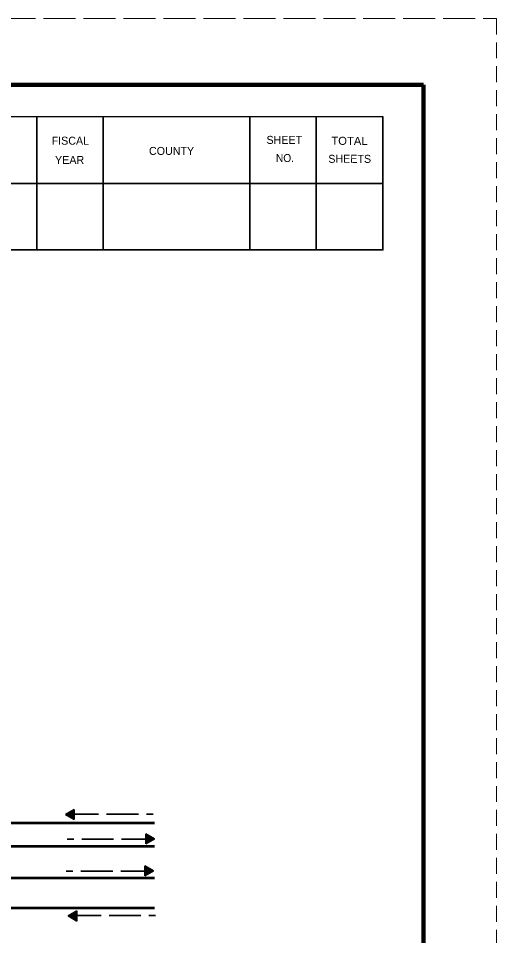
# Model space of a CAD drawing. Extents: x -58 to 622, y -372 to 68.
# Drawn here: x 549.8 to 621.6, y -69.7 to 68 of the extents above; entities that cross this region are included whole.
import ezdxf

# ---------------------------------------------------------------- set-up
doc = ezdxf.new("R2010")
doc.units = 0
doc.header["$LTSCALE"] = 0.8
doc.linetypes.add('LONG_DASHED', pattern=[7.5, 6, -1.5])
doc.linetypes.add('MEDIUM_DASHED', pattern=[4.5, 3, -1.5])
doc.layers.add('1', color=7, linetype='Continuous', lineweight=35)
doc.layers.add('61', color=7, linetype='Continuous', lineweight=35)

msp = doc.modelspace()

# ---------------------------------------------------------------- linework, layer by layer
at = {"layer": '1', "linetype": 'MEDIUM_DASHED', "lineweight": 13}
msp.add_line((621.5902, 67.9933), (621.5702, -372.0267), dxfattribs=at)
at = {"layer": '1'}
for p, q in [((558.1721, -50.7385), (556.8639, -51.4939)), ((557.8482, -52.0287), (557.8483, -50.9328)), ((557.8726, -52.0423), (557.8726, -50.919)), ((557.8971, -52.0561), (557.8971, -50.9051)), ((557.9055, -52.0607), (557.9056, -50.9003)), ((557.9422, -52.0815), (557.9424, -50.8794)), ((557.9652, -52.0943), (557.9652, -50.8665)), ((557.9791, -52.1021), (557.9792, -50.8587)), ((558.0013, -52.1145), (558.0013, -50.8461)), ((558.0364, -52.1343), (558.0364, -50.8262)), ((558.0632, -52.1493), (558.0632, -50.8109)), ((558.0952, -52.1674), (558.0952, -50.7928)), ((558.1089, -52.1749), (558.109, -50.7851)), ((558.1286, -52.1779), (558.1286, -50.788)), ((558.1503, -52.1983), (558.1503, -50.7616)), ((558.162, -52.2237), (558.1619, -50.7624)), ((558.1722, -52.2492), (558.1721, -50.7385)), ((558.1722, -52.2492), (556.8639, -51.4939)), ((556.915, -51.5046), (556.915, -51.4614)), ((556.9456, -51.5217), (556.9456, -51.444)), ((556.9711, -51.5359), (556.9711, -51.4296)), ((556.9909, -51.5471), (556.9908, -51.4184)), ((557.0132, -51.5596), (557.0132, -51.4057)), ((557.0269, -51.5674), (557.0268, -51.398)), ((557.0556, -51.5834), (557.0556, -51.3817)), ((557.1008, -51.6089), (557.1008, -51.3562)), ((557.1323, -51.6265), (557.1322, -51.3383)), ((557.1798, -51.6532), (557.1798, -51.3114)), ((557.2252, -51.6787), (557.2251, -51.2857)), ((557.254, -51.6948), (557.254, -51.2693)), ((557.2802, -51.7096), (557.2802, -51.2546)), ((557.3108, -51.7268), (557.311, -51.2372)), ((557.3392, -51.7428), (557.3393, -51.221)), ((557.3731, -51.7617), (557.3731, -51.202)), ((557.4037, -51.779), (557.4037, -51.1846)), ((557.4312, -51.7945), (557.4312, -51.1689)), ((557.4726, -51.8177), (557.4726, -51.1456)), ((557.4939, -51.8296), (557.494, -51.1333)), ((557.5322, -51.8511), (557.5322, -51.1118)), ((557.5675, -51.8708), (557.5672, -51.0918)), ((557.6078, -51.8937), (557.6078, -51.0689)), ((557.6461, -51.9151), (557.6462, -51.0472)), ((557.6735, -51.9305), (557.6734, -51.0317)), ((557.7005, -51.9457), (557.7005, -51.0163)), ((557.7273, -51.9606), (557.7273, -51.0013)), ((557.7441, -51.97), (557.7441, -50.9917)), ((557.7663, -51.9826), (557.7663, -50.979)), ((557.7898, -51.9958), (557.7899, -50.9659)), ((557.8175, -52.0113), (557.8176, -50.9501)), ((568.9053, -54.3872), (570.2136, -55.1424)), ((568.9053, -54.3872), (568.9054, -55.8978)), ((568.9155, -54.4127), (568.9156, -55.8739)), ((568.9272, -54.4381), (568.9272, -55.8747)), ((568.9489, -54.4584), (568.9489, -55.8483)), ((568.9686, -54.4614), (568.9685, -55.8513)), ((568.9823, -54.4689), (568.9823, -55.8435)), ((569.0143, -54.487), (569.0142, -55.8254)), ((569.0411, -54.5021), (569.0411, -55.8102)), ((569.0762, -54.5218), (569.0762, -55.7903)), ((569.0984, -54.5343), (569.0983, -55.7777)), ((569.1123, -54.542), (569.1123, -55.7698)), ((569.1352, -54.5548), (569.1351, -55.7569)), ((569.172, -54.5757), (569.1719, -55.736)), ((569.1804, -54.5802), (569.1804, -55.7312)), ((569.2049, -54.594), (569.2049, -55.7173)), ((569.2293, -54.6077), (569.2292, -55.7035)), ((569.26, -54.625), (569.2599, -55.6863)), ((569.2877, -54.6406), (569.2876, -55.6704)), ((569.3112, -54.6537), (569.3112, -55.6573)), ((569.3334, -54.6663), (569.3334, -55.6446)), ((569.3502, -54.6758), (569.3502, -55.635)), ((569.377, -54.6907), (569.377, -55.62)), ((569.404, -54.7058), (569.4041, -55.6046)), ((569.4314, -54.7212), (569.4313, -55.5891)), ((569.4697, -54.7426), (569.4697, -55.5674)), ((569.51, -54.7655), (569.5102, -55.5445)), ((569.5453, -54.7852), (569.5453, -55.5245)), ((569.5836, -54.8068), (569.5835, -55.503)), ((569.6049, -54.8187), (569.6049, -55.4907)), ((569.6463, -54.8418), (569.6463, -55.4674)), ((569.6738, -54.8573), (569.6738, -55.4517)), ((569.7044, -54.8746), (569.7044, -55.4343)), ((569.7382, -54.8936), (569.7382, -55.4153)), ((569.7667, -54.9095), (569.7665, -55.3992)), ((569.7973, -54.9267), (569.7973, -55.3817)), ((569.8235, -54.9415), (569.8235, -55.367)), ((569.8523, -54.9577), (569.8524, -55.3507)), ((569.8977, -54.9831), (569.8977, -55.3249)), ((569.9452, -55.0098), (569.9452, -55.298)), ((569.9767, -55.0274), (569.9767, -55.2802)), ((570.0219, -55.0529), (570.0219, -55.2546)), ((568.9054, -55.8978), (570.2136, -55.1424)), ((570.0506, -55.0689), (570.0507, -55.2383)), ((570.0643, -55.0767), (570.0643, -55.2306)), ((570.0866, -55.0892), (570.0867, -55.2179)), ((570.1064, -55.1004), (570.1064, -55.2067)), ((570.1319, -55.1146), (570.1319, -55.1923)), ((570.1625, -55.1317), (570.1625, -55.1749)), ((568.757, -59.1793), (570.0653, -59.9346)), ((568.757, -59.1793), (568.7572, -60.69)), ((568.7572, -60.69), (570.0653, -59.9346)), ((568.7672, -59.2048), (568.7673, -60.6661)), ((568.7789, -59.2302), (568.7789, -60.6669)), ((568.8007, -59.2506), (568.8007, -60.6405)), ((568.8203, -59.2536), (568.8202, -60.6434)), ((568.8341, -59.2611), (568.834, -60.6357)), ((568.8661, -59.2792), (568.866, -60.6176)), ((568.8928, -59.2942), (568.8928, -60.6023)), ((568.928, -59.314), (568.928, -60.5824)), ((568.9502, -59.3264), (568.9501, -60.5698)), ((568.964, -59.3342), (568.964, -60.562)), ((568.987, -59.347), (568.9868, -60.5491)), ((569.0237, -59.3678), (569.0237, -60.5282)), ((569.0322, -59.3724), (569.0322, -60.5234)), ((569.0567, -59.3862), (569.0567, -60.5095)), ((569.0811, -59.3998), (569.081, -60.4957)), ((569.1118, -59.4172), (569.1117, -60.4784)), ((569.1395, -59.4327), (569.1393, -60.4626)), ((569.1629, -59.4459), (569.163, -60.4495)), ((569.1852, -59.4585), (569.1852, -60.4367)), ((569.202, -59.4679), (569.202, -60.4272)), ((569.2287, -59.4828), (569.2287, -60.4122)), ((569.2558, -59.498), (569.2558, -60.3967)), ((569.2832, -59.5134), (569.2831, -60.3813)), ((569.3214, -59.5347), (569.3214, -60.3596)), ((569.3618, -59.5577), (569.362, -60.3367)), ((569.397, -59.5774), (569.397, -60.3167)), ((569.4353, -59.5989), (569.4352, -60.2952)), ((569.4567, -59.6108), (569.4567, -60.2829)), ((569.498, -59.634), (569.498, -60.2596)), ((569.5256, -59.6495), (569.5256, -60.2439)), ((569.5562, -59.6668), (569.5562, -60.2265)), ((569.59, -59.6857), (569.5899, -60.2075)), ((569.6184, -59.7017), (569.6182, -60.1913)), ((569.6491, -59.7189), (569.6491, -60.1739)), ((569.6753, -59.7337), (569.6753, -60.1592)), ((569.7041, -59.7498), (569.7042, -60.1428)), ((569.7495, -59.7752), (569.7494, -60.1171)), ((569.7969, -59.802), (569.797, -60.0902)), ((569.8284, -59.8196), (569.8284, -60.0723)), ((569.8737, -59.8451), (569.8737, -60.0467)), ((569.9023, -59.8611), (569.9024, -60.0305)), ((569.9161, -59.8689), (569.9161, -60.0227)), ((569.9383, -59.8814), (569.9384, -60.0101)), ((569.9582, -59.8926), (569.9582, -59.9989)), ((569.9837, -59.9067), (569.9837, -59.9845)), ((570.0142, -59.9239), (570.0142, -59.9671)), ((558.5672, -65.9547), (557.2591, -66.7101)), ((558.3742, -67.3182), (558.3743, -66.0748)), ((558.3964, -67.3307), (558.3964, -66.0622)), ((558.4316, -67.3504), (558.4316, -66.0423)), ((558.4583, -67.3655), (558.4584, -66.0271)), ((558.4903, -67.3836), (558.4904, -66.009)), ((558.5041, -67.3911), (558.5042, -66.0012)), ((558.5237, -67.3941), (558.5237, -66.0042)), ((558.5455, -67.4144), (558.5455, -65.9778)), ((558.5572, -67.4398), (558.5571, -65.9786)), ((558.5674, -67.4653), (558.5672, -65.9547)), ((558.5674, -67.4653), (557.2591, -66.7101)), ((557.3102, -66.7207), (557.3102, -66.6776)), ((557.3407, -66.7379), (557.3407, -66.6602)), ((557.3663, -66.7521), (557.3663, -66.6457)), ((557.3861, -66.7632), (557.386, -66.6346)), ((557.4083, -66.7758), (557.4083, -66.6219)), ((557.4221, -66.7836), (557.422, -66.6142)), ((557.4507, -66.7996), (557.4507, -66.5979)), ((557.496, -66.8251), (557.496, -66.5723)), ((557.5275, -66.8427), (557.5274, -66.5545)), ((557.5749, -66.8694), (557.575, -66.5276)), ((557.6203, -66.8948), (557.6202, -66.5018)), ((557.6492, -66.911), (557.6492, -66.4855)), ((557.6753, -66.9257), (557.6753, -66.4707)), ((557.706, -66.943), (557.7062, -66.4533)), ((557.7344, -66.9589), (557.7345, -66.4372)), ((557.7682, -66.9779), (557.7682, -66.4182)), ((557.7988, -66.9952), (557.7988, -66.4008)), ((557.8264, -67.0107), (557.8264, -66.3851)), ((557.8678, -67.0338), (557.8678, -66.3618)), ((557.8891, -67.0457), (557.8892, -66.3495)), ((557.9274, -67.0673), (557.9274, -66.328)), ((557.9627, -67.087), (557.9624, -66.308)), ((558.003, -67.1099), (558.003, -66.2851)), ((558.0412, -67.1312), (558.0413, -66.2634)), ((558.0687, -67.1467), (558.0686, -66.2479)), ((558.0957, -67.1618), (558.0957, -66.2325)), ((558.1224, -67.1767), (558.1224, -66.2175)), ((558.1392, -67.1862), (558.1392, -66.2079)), ((558.1615, -67.1988), (558.1614, -66.1952)), ((558.1849, -67.2119), (558.1851, -66.1821)), ((558.2127, -67.2275), (558.2128, -66.1662)), ((558.2433, -67.2448), (558.2434, -66.149)), ((558.2677, -67.2585), (558.2677, -66.1352)), ((558.2922, -67.2722), (558.2922, -66.1213)), ((558.3007, -67.2768), (558.3007, -66.1165)), ((558.3374, -67.2977), (558.3376, -66.0956)), ((558.3604, -67.3105), (558.3604, -66.0827))]:
    msp.add_line(p, q, dxfattribs=at)
at = {"layer": '1', "linetype": 'LONG_DASHED'}
for p, q in [((556.9931, -51.4437), (569.9931, -51.4437)), ((570.0844, -55.1927), (557.0844, -55.1927)), ((569.9362, -59.9848), (556.9362, -59.9848)), ((557.3882, -66.6598), (570.3882, -66.6598))]:
    msp.add_line(p, q, dxfattribs=at)
at = {"layer": '1', "lineweight": 53}
msp.add_line((517.2255, -61.0037), (570.2255, -61.0037), dxfattribs=at)
for points in [[(501.7255, 21.7462), (501.7255, -11.7538), (517.7255, -11.7538), (517.7255, 16.2462), (496.7255, 16.2462), (496.7255, -7.7538), (512.7255, -7.7538), (512.7255, 12.7462), (491.7255, 12.7462), (491.7255, -16.2538), (526.7255, -16.2538), (526.7255, -56.2537), (570.2255, -56.2537)], [(531.7255, 21.7462), (531.7255, -52.7537), (570.2255, -52.7537)], [(517.2255, -61.0037), (517.2255, -27.5038), (496.2255, -27.5038), (496.2255, -61.0037), (512.2255, -61.0037), (512.2255, -32.0037), (491.2255, -32.0037), (491.2255, -56.5037), (507.7255, -56.5037), (507.7255, -36.5037), (486.7255, -36.5037), (486.7255, -65.5037), (570.2255, -65.5037)]]:
    msp.add_lwpolyline(points, dxfattribs=at)
at = {"layer": '61', "linetype": 'LONG_DASHED', "lineweight": 13}
msp.add_line((-58.4297, 67.9933), (621.5902, 67.9933), dxfattribs=at)
at = {"layer": '61', "lineweight": 158}
msp.add_line((610.6102, 57.9933), (610.6302, -362.0467), dxfattribs=at)
at = {"layer": '61'}
for p, q in [((552.5303, 53.2333), (552.5303, 33.2333)), ((562.5303, 53.2333), (562.5303, 33.2333)), ((584.5102, 53.2533), (584.5102, 33.2533)), ((594.5102, 53.2533), (594.5102, 33.2533)), ((604.5303, 43.2133), (496.5102, 43.2333))]:
    msp.add_line(p, q, dxfattribs=at)
at = {"layer": '61', "lineweight": 158}
msp.add_lwpolyline([(610.6102, 57.9933), (-28.4297, 57.9933), (-28.4297, -362.0267)], dxfattribs=at)
at = {"layer": '61'}
for points in [[(604.5102, 53.2533), (496.5302, 53.2333), (496.5302, 33.2333)], [(604.5102, 53.2533), (604.5102, 33.2533), (496.5302, 33.2333)]]:
    msp.add_lwpolyline(points, dxfattribs=at)

# ---------------------------------------------------------------- texts
for s, rotation, p in [('FISCAL', 359.942, (554.7703, 49.0333)), ('SHEET', 0.059, (587.0303, 49.1533)), ('COUNTY', 0.069, (569.3903, 47.4933)), ('YEAR', 0.105, (555.2903, 46.1333)), ('SHEETS', 359.959, (596.3102, 46.3133))]:
    msp.add_text(s, height=1.201, rotation=rotation, dxfattribs=at).set_placement(p)
for s, rotation, width, p in [('TOTAL', 359.926, 1.05, (596.7703, 49.0133)), ('NO.', 359.852, 0.95, (588.4502, 46.4333))]:
    msp.add_text(s, height=1.201, rotation=rotation, dxfattribs=dict(at, width=width)).set_placement(p)

doc.saveas('drawing.dxf')
